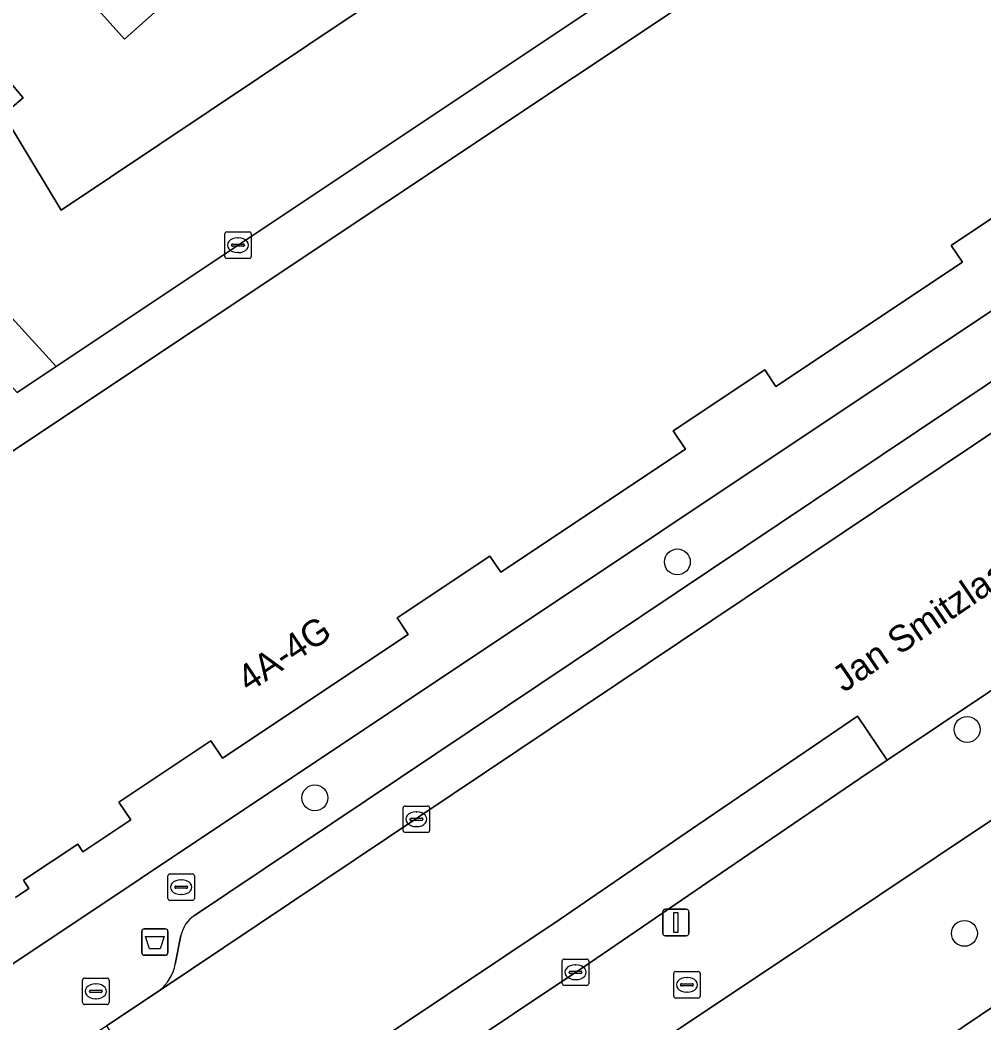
# Model space of a CAD drawing. Extents: x 161087 to 161926, y 382572 to 383873.
# Drawn here: x 161655.32 to 161691.75, y 382664.14 to 382702.05 of the extents above; entities that cross this region are included whole.
import ezdxf

# ---------------------------------------------------------------- set-up
doc = ezdxf.new("R2010")
doc.units = 0
for name, color, linetype in [('IMGEO_Afvalbak', 7, 'Continuous'), ('IMGEO_Boom', 7, 'Continuous'), ('IMGEO_Brandkraan', 7, 'Continuous'), ('IMGEO_Erf', 7, 'Continuous'), ('IMGEO_Groenvoorziening', 7, 'Continuous'), ('IMGEO_Kolk', 7, 'Continuous'), ('IMGEO_Lichtmast', 7, 'Continuous'), ('IMGEO_Openbare_ruimte_label', 7, 'Continuous'), ('IMGEO_Pand', 7, 'Continuous'), ('IMGEO_Pand_nummerreeks', 7, 'Continuous'), ('IMGEO_Parkeervlak_open', 7, 'Continuous'), ('IMGEO_Rijbaan_lokaal_open', 7, 'Continuous'), ('IMGEO_Rioolput', 7, 'Continuous'), ('IMGEO_Terreindeel_open', 7, 'Continuous'), ('IMGEO_Voetpad_open', 7, 'Continuous')]:
    doc.layers.add(name, color=color, linetype=linetype)

msp = doc.modelspace()

# ---------------------------------------------------------------- linework, layer by layer
at = {"layer": 'IMGEO_Afvalbak'}
for p, q in [((161660.015, 382667.695), (161660.805, 382667.695)), ((161660.805, 382667.695), (161660.015, 382667.695)), ((161659.915, 382666.795), (161659.915, 382667.595)), ((161659.915, 382667.595), (161659.915, 382666.795)), ((161660.905, 382667.595), (161660.905, 382666.795)), ((161660.905, 382666.795), (161660.905, 382667.595)), ((161660.805, 382666.695), (161660.015, 382666.695)), ((161660.015, 382666.695), (161660.805, 382666.695))]:
    msp.add_line(p, q, dxfattribs=at)
msp.add_lwpolyline([(161660.058, 382667.409), (161660.762, 382667.409), (161660.613, 382666.939), (161660.207, 382666.939), (161660.058, 382667.409)], dxfattribs=at)
for centre, start, end in [((161660.015, 382667.595), 90, 180), ((161660.015, 382667.595), 90, 180), ((161660.805, 382667.595), 0, 90), ((161660.805, 382667.595), 360, 90), ((161660.015, 382666.795), 180, 270), ((161660.015, 382666.795), 180, 270), ((161660.805, 382666.795), 270, 0), ((161660.805, 382666.795), 270, 0)]:
    msp.add_arc(centre, 0.1, start, end, dxfattribs=at)
at = {"layer": 'IMGEO_Boom'}
for centre in [(161680.161, 382681.567), (161691.111, 382675.233), (161666.46, 382672.645), (161691.009, 382667.523)]:
    msp.add_circle(centre, 0.489, dxfattribs=at)
at = {"layer": 'IMGEO_Brandkraan'}
for p, q in [((161660.905, 382668.844), (161660.905, 382669.696)), ((161660.98, 382669.77), (161661.832, 382669.77)), ((161661.393, 382669.55), (161661.418, 382669.55)), ((161661.906, 382669.696), (161661.906, 382668.844)), ((161661.164, 382669.264), (161661.164, 382669.276)), ((161661.602, 382669.227), (161661.204, 382669.227)), ((161661.207, 382669.313), (161661.605, 382669.313)), ((161661.648, 382669.276), (161661.648, 382669.264)), ((161661.832, 382668.77), (161660.98, 382668.77)), ((161661.416, 382668.99), (161661.391, 382668.99))]:
    msp.add_line(p, q, dxfattribs=at)
for points in [[(161660.905, 382668.844), (161660.905, 382669.696)], [(161660.98, 382669.77), (161661.832, 382669.77)], [(161661.906, 382669.696), (161661.906, 382668.844)], [(161661.832, 382668.77), (161660.98, 382668.77)]]:
    msp.add_lwpolyline(points, dxfattribs=at)
for centre, radius, start, end in [((161660.982, 382669.694), 0.0765, 91.552, 178.448), ((161660.982, 382669.694), 0.0765, 91.552, 178.448), ((161661.83, 382669.694), 0.0765, 1.552, 88.448), ((161661.83, 382669.694), 0.0765, 1.552, 88.448), ((161661.204, 382669.273), 0.0403, 85.8775, 175.7526), ((161661.201, 382669.263), 0.0366, 178.938, 274.7102), ((161661.605, 382669.27), 0.043, 264.8664, 352.4533), ((161661.609, 382669.275), 0.0386, 1.7309, 96.639), ((161660.982, 382668.846), 0.0765, 181.552, 268.448), ((161660.982, 382668.846), 0.0765, 181.552, 268.448), ((161661.83, 382668.846), 0.0765, 271.552, 358.448), ((161661.83, 382668.846), 0.0765, 271.552, 358.448)]:
    msp.add_arc(centre, radius, start, end, dxfattribs=at)
for centre, major_axis, ratio, start_param, end_param in [((161661.392, 382669.27), (-0.387, 0.002), 0.722429, 4.712389, 7.853982), ((161661.417, 382669.27), (-0.39, 0.002), 0.717154, 1.570796, 4.712389)]:
    msp.add_ellipse(centre, major_axis=major_axis, ratio=ratio, start_param=start_param, end_param=end_param, dxfattribs=at)
at = {"layer": 'IMGEO_Erf'}
for points in [[(161735.255, 382701.021), (161732.962, 382699.466), (161731.689, 382698.619), (161728.763, 382696.666), (161727.938, 382696.115), (161725.531, 382694.508), (161718.244, 382689.485), (161701.091, 382677.661), (161701.029, 382677.802), (161699.806, 382676.99), (161692.19, 382671.902), (161685.571, 382667.484), (161684.546, 382666.8), (161679.878, 382663.684), (161678.967, 382663.076), (161676.16, 382661.202), (161674.931, 382660.382), (161671.581, 382658.146), (161671.236, 382657.915), (161664.134, 382653.175)], [(161650.008, 382663.023), (161699.247, 382695.877), (161698.104, 382697.591), (161694.427, 382695.14), (161693.965, 382695.834), (161690.512, 382693.533), (161690.937, 382692.895), (161683.888, 382688.196), (161683.465, 382688.829), (161680.008, 382686.525), (161680.47, 382685.832), (161673.485, 382681.175), (161673.077, 382681.786), (161669.572, 382679.45), (161669.988, 382678.826), (161662.965, 382674.144), (161662.524, 382674.806), (161659.048, 382672.489), (161659.499, 382671.812), (161657.692, 382670.607), (161657.496, 382670.901), (161655.445, 382669.534), (161655.654, 382669.221), (161655.143, 382668.881)], [(161679.583, 382641.37), (161672.727, 382651.507), (161689.091, 382662.531), (161688.997, 382662.671), (161720.365, 382683.794), (161720.728, 382683.254), (161722.721, 382684.597), (161724.341, 382682.191), (161722.345, 382680.847), (161724.856, 382677.117), (161723.424, 382676.152), (161735.976, 382657.583), (161736.092, 382657.661), (161736.443, 382657.138), (161736.26, 382657.015), (161738.5, 382653.672), (161738.683, 382653.795), (161741.783, 382649.168), (161741.678, 382649.096), (161742.234, 382648.258), (161741.213, 382647.581), (161741.875, 382646.56), (161729.232, 382638.832)]]:
    msp.add_lwpolyline(points, dxfattribs=at)
at = {"layer": 'IMGEO_Groenvoorziening'}
msp.add_lwpolyline([(161660.241, 382707.326), (161659.272, 382708.827), (161658.818, 382708.421), (161655.544, 382705.493), (161659.264, 382701.333), (161662.336, 382704.08)], close=True, dxfattribs=at)
at = {"layer": 'IMGEO_Kolk'}
for p, q in [((161663.055, 382693.117), (161663.055, 382693.969)), ((161663.13, 382694.043), (161663.982, 382694.043)), ((161663.543, 382693.823), (161663.568, 382693.823)), ((161664.056, 382693.969), (161664.056, 382693.117)), ((161663.314, 382693.537), (161663.314, 382693.549)), ((161663.752, 382693.5), (161663.354, 382693.5)), ((161663.357, 382693.586), (161663.755, 382693.586)), ((161663.798, 382693.549), (161663.798, 382693.537)), ((161663.982, 382693.043), (161663.13, 382693.043)), ((161663.566, 382693.263), (161663.541, 382693.263)), ((161669.796, 382671.412), (161669.796, 382672.264)), ((161669.871, 382672.338), (161670.723, 382672.338)), ((161670.797, 382672.264), (161670.797, 382671.412)), ((161670.055, 382671.832), (161670.055, 382671.844)), ((161670.098, 382671.881), (161670.496, 382671.881)), ((161670.284, 382672.118), (161670.309, 382672.118)), ((161670.539, 382671.844), (161670.539, 382671.832)), ((161670.493, 382671.795), (161670.095, 382671.795)), ((161670.307, 382671.558), (161670.282, 382671.558)), ((161670.723, 382671.338), (161669.871, 382671.338)), ((161675.887, 382666.552), (161676.739, 382666.552)), ((161675.812, 382665.626), (161675.812, 382666.478)), ((161676.3, 382666.332), (161676.325, 382666.332)), ((161676.813, 382666.478), (161676.813, 382665.626)), ((161676.071, 382666.046), (161676.071, 382666.058)), ((161676.509, 382666.009), (161676.111, 382666.009)), ((161676.114, 382666.095), (161676.512, 382666.095)), ((161676.323, 382665.772), (161676.298, 382665.772)), ((161676.555, 382666.058), (161676.555, 382666.046)), ((161676.739, 382665.552), (161675.887, 382665.552))]:
    msp.add_line(p, q, dxfattribs=at)
for points in [[(161663.055, 382693.117), (161663.055, 382693.969)], [(161663.13, 382694.043), (161663.982, 382694.043)], [(161664.056, 382693.969), (161664.056, 382693.117)], [(161663.982, 382693.043), (161663.13, 382693.043)], [(161669.796, 382671.412), (161669.796, 382672.264)], [(161669.871, 382672.338), (161670.723, 382672.338)], [(161670.797, 382672.264), (161670.797, 382671.412)], [(161670.723, 382671.338), (161669.871, 382671.338)], [(161675.887, 382666.552), (161676.739, 382666.552)], [(161675.812, 382665.626), (161675.812, 382666.478)], [(161676.813, 382666.478), (161676.813, 382665.626)], [(161676.739, 382665.552), (161675.887, 382665.552)]]:
    msp.add_lwpolyline(points, dxfattribs=at)
for centre, radius, start, end in [((161663.132, 382693.967), 0.0765, 91.552, 178.448), ((161663.132, 382693.967), 0.0765, 91.552, 178.448), ((161663.98, 382693.967), 0.0765, 1.552, 88.448), ((161663.98, 382693.967), 0.0765, 1.552, 88.448), ((161663.354, 382693.546), 0.0403, 85.8775, 175.7526), ((161663.351, 382693.536), 0.0366, 178.938, 274.7102), ((161663.755, 382693.543), 0.043, 264.8664, 352.4533), ((161663.759, 382693.548), 0.0386, 1.7309, 96.639), ((161663.132, 382693.119), 0.0765, 181.552, 268.448), ((161663.132, 382693.119), 0.0765, 181.552, 268.448), ((161663.98, 382693.119), 0.0765, 271.552, 358.448), ((161663.98, 382693.119), 0.0765, 271.552, 358.448), ((161669.873, 382672.262), 0.0765, 91.552, 178.448), ((161669.873, 382672.262), 0.0765, 91.552, 178.448), ((161670.721, 382672.262), 0.0765, 1.552, 88.448), ((161670.721, 382672.262), 0.0765, 1.552, 88.448), ((161670.095, 382671.841), 0.0403, 85.8775, 175.7526), ((161670.092, 382671.831), 0.0366, 178.938, 274.7102), ((161670.496, 382671.838), 0.043, 264.8664, 352.4533), ((161670.5, 382671.843), 0.0386, 1.7309, 96.639), ((161669.873, 382671.414), 0.0765, 181.552, 268.448), ((161669.873, 382671.414), 0.0765, 181.552, 268.448), ((161670.721, 382671.414), 0.0765, 271.552, 358.448), ((161670.721, 382671.414), 0.0765, 271.552, 358.448), ((161675.889, 382666.476), 0.0765, 91.552, 178.448), ((161675.889, 382666.476), 0.0765, 91.552, 178.448), ((161676.737, 382666.476), 0.0765, 1.552, 88.448), ((161676.737, 382666.476), 0.0765, 1.552, 88.448), ((161676.111, 382666.055), 0.0403, 85.8775, 175.7526), ((161676.108, 382666.045), 0.0366, 178.938, 274.7102), ((161676.512, 382666.052), 0.043, 264.8664, 352.4533), ((161676.516, 382666.057), 0.0386, 1.7309, 96.639), ((161675.889, 382665.628), 0.0765, 181.552, 268.448), ((161675.889, 382665.628), 0.0765, 181.552, 268.448), ((161676.737, 382665.628), 0.0765, 271.552, 358.448), ((161676.737, 382665.628), 0.0765, 271.552, 358.448)]:
    msp.add_arc(centre, radius, start, end, dxfattribs=at)
for centre, major_axis, ratio, start_param, end_param in [((161663.542, 382693.543), (-0.387, 0.002), 0.722429, 4.712389, 7.853982), ((161663.567, 382693.543), (-0.39, 0.002), 0.717154, 1.570796, 4.712389), ((161670.283, 382671.838), (-0.387, 0.002), 0.722429, 4.712389, 7.853982), ((161670.308, 382671.838), (-0.39, 0.002), 0.717154, 1.570796, 4.712389), ((161676.299, 382666.052), (-0.387, 0.002), 0.722429, 4.712389, 7.853982), ((161676.324, 382666.052), (-0.39, 0.002), 0.717154, 1.570796, 4.712389)]:
    msp.add_ellipse(centre, major_axis=major_axis, ratio=ratio, start_param=start_param, end_param=end_param, dxfattribs=at)
at = {"layer": 'IMGEO_Lichtmast'}
for p, q in [((161679.709, 382668.434), (161680.499, 382668.434)), ((161680.499, 382668.434), (161679.709, 382668.434)), ((161679.609, 382667.534), (161679.609, 382668.334)), ((161679.609, 382668.334), (161679.609, 382667.534)), ((161680.599, 382668.334), (161680.599, 382667.534)), ((161680.599, 382667.534), (161680.599, 382668.334)), ((161680.499, 382667.434), (161679.709, 382667.434)), ((161679.709, 382667.434), (161680.499, 382667.434))]:
    msp.add_line(p, q, dxfattribs=at)
msp.add_lwpolyline([(161680.029, 382668.309), (161680.179, 382668.309), (161680.179, 382667.559), (161680.029, 382667.559), (161680.029, 382668.309)], dxfattribs=at)
for centre, start, end in [((161679.709, 382668.334), 90, 180), ((161679.709, 382668.334), 90, 180), ((161680.499, 382668.334), 0, 90), ((161680.499, 382668.334), 360, 90), ((161679.709, 382667.534), 180, 270), ((161679.709, 382667.534), 180, 270), ((161680.499, 382667.534), 270, 0), ((161680.499, 382667.534), 270, 0)]:
    msp.add_arc(centre, 0.1, start, end, dxfattribs=at)
at = {"layer": 'IMGEO_Pand'}
for points in [[(161655.143, 382668.881), (161655.654, 382669.221), (161655.445, 382669.534), (161657.496, 382670.901), (161657.692, 382670.607), (161659.499, 382671.812), (161659.048, 382672.489), (161662.524, 382674.806), (161662.965, 382674.144), (161669.988, 382678.826), (161669.572, 382679.45), (161673.077, 382681.786), (161673.485, 382681.175), (161680.47, 382685.832), (161680.008, 382686.525), (161683.465, 382688.829), (161683.888, 382688.196), (161690.937, 382692.895), (161690.512, 382693.533), (161693.965, 382695.834), (161694.427, 382695.14), (161698.104, 382697.591), (161691.115, 382708.074)], [(161683.371, 382704.641), (161654.886, 382685.652)], [(161729.232, 382638.832), (161741.875, 382646.56), (161741.213, 382647.581), (161742.234, 382648.258), (161741.678, 382649.096), (161741.783, 382649.168), (161738.683, 382653.795), (161738.5, 382653.672), (161736.26, 382657.015), (161736.443, 382657.138), (161736.092, 382657.661), (161735.976, 382657.583), (161723.424, 382676.152), (161724.856, 382677.117), (161722.345, 382680.847), (161724.341, 382682.191), (161722.721, 382684.597), (161720.728, 382683.254), (161720.365, 382683.794), (161688.997, 382662.671), (161689.091, 382662.531), (161672.727, 382651.507), (161679.583, 382641.37)]]:
    msp.add_lwpolyline(points, dxfattribs=at)
at = {"layer": 'IMGEO_Parkeervlak_open'}
for points in [[(161686.783, 382714.893), (161682.173, 382721.921), (161660.241, 382707.326), (161662.336, 382704.08), (161659.264, 382701.333), (161655.544, 382705.493), (161658.818, 382708.421), (161640.645, 382728.413), (161633.825, 382723.334), (161652.223, 382702.935), (161655.434, 382699.108), (161654.688, 382698.482), (161656.868, 382694.863)], [(161688.094, 382674.073), (161686.973, 382675.729), (161685.938, 382675.035), (161680.939, 382671.625), (161675.735, 382668.065), (161662.924, 382659.486), (161664.046, 382657.83), (161669.097, 382661.212), (161673.973, 382664.478), (161676.856, 382666.409), (161682.067, 382669.974), (161687.058, 382673.378)]]:
    msp.add_lwpolyline(points, close=True, dxfattribs=at)
for points in [[(161660.57, 382665.356), (161699.988, 382691.772)], [(161697.021, 382691.73), (161661.905, 382668.197)], [(161661.399, 382667.438), (161661.183, 382666.363)]]:
    msp.add_lwpolyline(points, dxfattribs=at)
for centre, radius, start, end in [((161662.572, 382667.204), 1.196, 123.8844, 168.7354), ((161659.601, 382666.636), 1.605, 307.1253, 350.2137)]:
    msp.add_arc(centre, radius, start, end, dxfattribs=at)
at = {"layer": 'IMGEO_Rijbaan_lokaal_open'}
for points in [[(161652.162, 382693.908), (161656.689, 382688.957), (161689.336, 382710.75), (161691.115, 382708.074), (161698.104, 382697.591), (161699.247, 382695.877), (161703.457, 382698.746), (161700.929, 382702.454), (161682.663, 382729.735), (161659.826, 382716.672), (161645.915, 382732.339)], [(161640.645, 382728.413), (161658.818, 382708.421), (161659.272, 382708.827), (161660.241, 382707.326), (161682.173, 382721.921), (161686.783, 382714.893), (161656.868, 382694.863), (161654.688, 382698.482), (161655.434, 382699.108), (161652.223, 382702.935)], [(161717.203, 382703.237), (161706.678, 382696.36), (161701.807, 382693.056), (161700.182, 382691.91), (161699.988, 382691.772), (161660.57, 382665.356), (161658.586, 382664.031), (161663.174, 382657.246), (161664.046, 382657.83), (161662.924, 382659.486), (161675.735, 382668.065), (161680.939, 382671.625), (161685.938, 382675.035), (161686.973, 382675.729), (161688.094, 382674.073), (161693.868, 382677.944), (161698.929, 382681.367), (161703.962, 382684.791), (161710.791, 382689.395), (161721.919, 382696.655), (161726.08, 382699.414), (161730.343, 382702.265)]]:
    msp.add_lwpolyline(points, dxfattribs=at)
at = {"layer": 'IMGEO_Rioolput'}
for p, q in [((161657.682, 382664.906), (161657.682, 382665.758)), ((161657.757, 382665.832), (161658.609, 382665.832)), ((161658.683, 382665.758), (161658.683, 382664.906)), ((161680.023, 382665.151), (161680.023, 382666.003)), ((161680.098, 382666.077), (161680.95, 382666.077)), ((161680.511, 382665.857), (161680.536, 382665.857)), ((161681.024, 382666.003), (161681.024, 382665.151)), ((161657.984, 382665.375), (161658.382, 382665.375)), ((161658.17, 382665.612), (161658.195, 382665.612)), ((161680.282, 382665.571), (161680.282, 382665.583)), ((161680.72, 382665.534), (161680.322, 382665.534)), ((161680.325, 382665.62), (161680.723, 382665.62)), ((161680.766, 382665.583), (161680.766, 382665.571)), ((161657.941, 382665.326), (161657.941, 382665.338)), ((161658.379, 382665.289), (161657.981, 382665.289)), ((161658.193, 382665.052), (161658.168, 382665.052)), ((161658.425, 382665.338), (161658.425, 382665.326)), ((161680.95, 382665.077), (161680.098, 382665.077)), ((161680.534, 382665.297), (161680.509, 382665.297)), ((161658.609, 382664.832), (161657.757, 382664.832))]:
    msp.add_line(p, q, dxfattribs=at)
for points in [[(161657.682, 382664.906), (161657.682, 382665.758)], [(161657.757, 382665.832), (161658.609, 382665.832)], [(161658.683, 382665.758), (161658.683, 382664.906)], [(161680.023, 382665.151), (161680.023, 382666.003)], [(161680.098, 382666.077), (161680.95, 382666.077)], [(161681.024, 382666.003), (161681.024, 382665.151)], [(161680.95, 382665.077), (161680.098, 382665.077)], [(161658.609, 382664.832), (161657.757, 382664.832)]]:
    msp.add_lwpolyline(points, dxfattribs=at)
for centre, radius, start, end in [((161657.759, 382665.756), 0.0765, 91.552, 178.448), ((161657.759, 382665.756), 0.0765, 91.552, 178.448), ((161658.607, 382665.756), 0.0765, 1.552, 88.448), ((161658.607, 382665.756), 0.0765, 1.552, 88.448), ((161680.1, 382666.001), 0.0765, 91.552, 178.448), ((161680.1, 382666.001), 0.0765, 91.552, 178.448), ((161680.948, 382666.001), 0.0765, 1.552, 88.448), ((161680.948, 382666.001), 0.0765, 1.552, 88.448), ((161657.981, 382665.335), 0.0403, 85.8775, 175.7526), ((161658.386, 382665.337), 0.0386, 1.7309, 96.639), ((161680.322, 382665.58), 0.0403, 85.8775, 175.7526), ((161680.319, 382665.57), 0.0366, 178.938, 274.7102), ((161680.723, 382665.577), 0.043, 264.8664, 352.4533), ((161680.727, 382665.582), 0.0386, 1.7309, 96.639), ((161657.978, 382665.325), 0.0366, 178.938, 274.7102), ((161658.382, 382665.332), 0.043, 264.8664, 352.4533), ((161680.1, 382665.153), 0.0765, 181.552, 268.448), ((161680.1, 382665.153), 0.0765, 181.552, 268.448), ((161680.948, 382665.153), 0.0765, 271.552, 358.448), ((161680.948, 382665.153), 0.0765, 271.552, 358.448), ((161657.759, 382664.908), 0.0765, 181.552, 268.448), ((161657.759, 382664.908), 0.0765, 181.552, 268.448), ((161658.607, 382664.908), 0.0765, 271.552, 358.448), ((161658.607, 382664.908), 0.0765, 271.552, 358.448)]:
    msp.add_arc(centre, radius, start, end, dxfattribs=at)
for centre, major_axis, ratio, start_param, end_param in [((161680.51, 382665.577), (-0.387, 0.002), 0.722429, 4.712389, 7.853982), ((161680.535, 382665.577), (-0.39, 0.002), 0.717154, 1.570796, 4.712389), ((161658.169, 382665.332), (-0.387, 0.002), 0.722429, 4.712389, 7.853982), ((161658.194, 382665.332), (-0.39, 0.002), 0.717154, 1.570796, 4.712389)]:
    msp.add_ellipse(centre, major_axis=major_axis, ratio=ratio, start_param=start_param, end_param=end_param, dxfattribs=at)
at = {"layer": 'IMGEO_Terreindeel_open'}
msp.add_lwpolyline([(161656.689, 382688.957), (161652.162, 382693.908), (161650.887, 382692.734), (161655.206, 382687.967)], close=True, dxfattribs=at)
at = {"layer": 'IMGEO_Voetpad_open'}
for points in [[(161713.52, 382710.932), (161700.929, 382702.454), (161703.457, 382698.746), (161699.247, 382695.877), (161650.008, 382663.023), (161649.374, 382662.6), (161651.703, 382659.86)], [(161740.078, 382708.641), (161738.609, 382707.751), (161734.831, 382705.246), (161734.718, 382705.171), (161731.947, 382703.33), (161730.343, 382702.265), (161730.62, 382701.85), (161726.357, 382698.999), (161726.08, 382699.414), (161721.919, 382696.655), (161710.791, 382689.395), (161703.962, 382684.791), (161698.929, 382681.367), (161693.868, 382677.944), (161688.094, 382674.073), (161687.058, 382673.378), (161682.067, 382669.974), (161676.856, 382666.409), (161673.973, 382664.478), (161669.097, 382661.212), (161664.046, 382657.83), (161663.174, 382657.246), (161660.282, 382655.309), (161659.549, 382654.818)], [(161661.905, 382668.197), (161697.021, 382691.73)], [(161664.134, 382653.175), (161671.236, 382657.915), (161671.581, 382658.146), (161674.931, 382660.382), (161676.16, 382661.202), (161678.967, 382663.076), (161679.878, 382663.684), (161684.546, 382666.8), (161685.571, 382667.484), (161692.19, 382671.902), (161699.806, 382676.99), (161701.029, 382677.802), (161701.091, 382677.661), (161718.244, 382689.485)], [(161661.183, 382666.363), (161661.399, 382667.438)], [(161654.342, 382661.196), (161655.686, 382662.094), (161658.586, 382664.031), (161660.57, 382665.356)]]:
    msp.add_lwpolyline(points, dxfattribs=at)
msp.add_lwpolyline([(161683.371, 382704.641), (161683.55, 382704.552), (161686.736, 382706.676), (161687.438, 382705.623), (161691.115, 382708.074), (161689.336, 382710.75), (161656.689, 382688.957), (161655.206, 382687.967), (161650.887, 382692.734), (161652.162, 382693.908), (161650.622, 382695.592), (161647.175, 382692.39), (161653.956, 382685.031), (161654.648, 382685.492), (161649.237, 382691.365), (161649.445, 382691.558), (161654.886, 382685.652)], close=True, dxfattribs=at)
for centre, radius, start, end in [((161662.572, 382667.204), 1.196, 123.8844, 168.7354), ((161659.601, 382666.636), 1.605, 307.1253, 350.2137)]:
    msp.add_arc(centre, radius, start, end, dxfattribs=at)

# ---------------------------------------------------------------- texts
at = {"layer": 'IMGEO_Openbare_ruimte_label'}
msp.add_text('Jan Smitzlaan', height=1, rotation=34.1986, dxfattribs=at).set_placement((161686.453, 382676.607))
at = {"layer": 'IMGEO_Pand_nummerreeks'}
msp.add_text('4A-4G', height=1, rotation=33.6899, dxfattribs=at).set_placement((161663.96, 382676.61))

doc.saveas('drawing.dxf')
